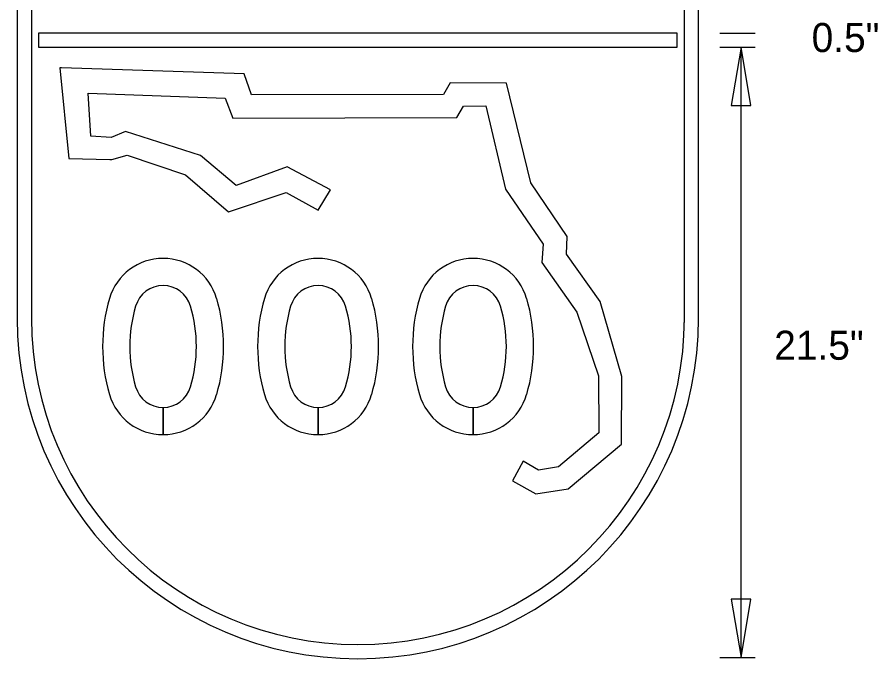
# Model space of a CAD drawing. Extents: x 0 to 770, y 0 to 495.
# Drawn here: x 659.4 to 763, y 209.5 to 286.8 of the extents above; entities that cross this region are included whole.
import ezdxf

# ---------------------------------------------------------------- set-up
doc = ezdxf.new("R2010")
doc.units = 0
for name, color, linetype in [('Default', 7, 'Continuous'), ('Dimension', 7, 'Continuous'), ('GSBWFill', 7, 'Continuous'), ('GSColorFill', 7, 'Continuous'), ('GSDims', 7, 'Continuous'), ('GSOutline', 7, 'Continuous'), ('IndexDetail_0', 7, 'Continuous'), ('TextStructures', 7, 'Continuous')]:
    doc.layers.add(name, color=color, linetype=linetype)

msp = doc.modelspace()

# ---------------------------------------------------------------- linework, layer by layer
at = {"layer": 'Default'}
for points in [[(664.53, 280.66), (665.6, 269.75), (670.52, 269.6)], [(664.71, 280.65), (664.53, 280.65)], [(719.01, 230.91), (721.8, 229.36), (725.71, 229.94), (732.12, 235.35), (732.16, 243.49), (729.56, 252.52), (725.53, 258.22), (725.61, 260.34), (721.2, 266.81), (718.29, 278.82), (711.52, 278.86), (710.72, 277.43), (687.6, 277.4), (686.7, 279.95), (664.71, 280.65)], [(670.76, 269.6), (672.6, 270.13), (679.65, 267.78), (684.8, 263.33), (691.76, 265.66), (695.61, 263.52), (697.08, 265.97), (691.88, 268.73), (685.73, 266.49), (681.45, 270.11), (672.42, 272.98), (670.7, 272.28), (668.24, 272.44), (667.92, 277.59), (684.43, 277), (685.34, 274.61), (712.29, 274.69)], [(712.29, 274.69), (713.1, 276.06), (715.81, 276.1), (718.18, 266.03), (722.7, 259.41), (722.54, 257.2), (726.76, 251.23), (729.36, 243.57)], [(670.52, 269.6), (670.76, 269.6)], [(729.36, 243.57), (729.4, 236.69)], [(729.4, 236.69), (724.56, 232.61), (722.13, 232.21), (720.29, 233.27), (719.01, 230.91)]]:
    msp.add_lwpolyline(points, dxfattribs=at)
at = {"layer": 'Dimension'}
for points in [[(746.53, 283.14), (745.35, 276.12), (747.72, 276.12)], [(746.53, 209.66), (747.72, 216.67), (745.35, 216.67)]]:
    msp.add_lwpolyline(points, close=True, dxfattribs=at)
at = {"layer": 'GSBWFill'}
for p, q in [((659.38, 300.06), (659.38, 250.5)), ((661.09, 300.06), (661.09, 250.5)), ((739.7, 249.97), (739.7, 300.06)), ((741.41, 250.27), (741.41, 300.06)), ((738.84, 284.85), (661.94, 284.85)), ((661.94, 284.85), (661.94, 283.14)), ((738.84, 283.14), (738.84, 284.85)), ((661.94, 283.14), (738.84, 283.14)), ((676.94, 239.77), (676.94, 236.49)), ((676.94, 236.49), (676.94, 239.77)), ((695.6, 239.77), (695.6, 236.49)), ((695.6, 236.49), (695.6, 239.77)), ((714.26, 236.49), (714.26, 239.77)), ((714.27, 239.77), (714.27, 236.49))]:
    msp.add_line(p, q, dxfattribs=at)
for centre, radius, start, end in [((676.94, 250.99), 6.72, 16.4025, 163.5975), ((695.6, 250.99), 6.72, 16.4025, 163.5975), ((714.26, 250.99), 6.72, 16.4025, 163.5975), ((676.94, 250.99), 3.44, 16.4025, 163.5975), ((695.6, 250.99), 3.44, 16.4025, 163.5975), ((714.26, 250.99), 3.44, 16.4025, 163.5975), ((690.17, 247.1), 20.51, 163.5975, 196.4025), ((663.72, 247.1), 20.51, 343.5975, 16.4025), ((708.83, 247.1), 20.51, 163.5975, 196.4025), ((682.38, 247.1), 20.51, 343.5975, 16.4025), ((727.49, 247.1), 20.51, 163.5975, 196.4025), ((701.04, 247.1), 20.51, 343.5975, 16.4025), ((690.17, 247.1), 17.23, 163.5975, 196.4025), ((663.72, 247.1), 17.23, 343.5975, 16.4025), ((708.83, 247.1), 17.23, 163.5975, 196.4025), ((682.38, 247.1), 17.23, 343.5975, 16.4025), ((727.49, 247.1), 17.23, 163.5975, 196.4025), ((701.04, 247.1), 17.23, 343.5975, 16.4025), ((676.94, 243.2), 3.44, 196.4025, 270), ((676.94, 243.2), 3.44, 270.0171, 343.5975), ((695.6, 243.2), 3.44, 196.4025, 270), ((695.6, 243.2), 3.44, 270.0171, 343.5975), ((714.26, 243.2), 3.44, 196.4025, 270), ((714.26, 243.2), 3.44, 270.0171, 343.5975), ((676.94, 243.2), 6.72, 196.4025, 270), ((676.94, 243.2), 6.72, 270.0087, 343.5975), ((695.6, 243.2), 6.72, 196.4025, 270), ((695.6, 243.2), 6.72, 270.0087, 343.5975), ((714.26, 243.2), 6.72, 196.4025, 270), ((714.26, 243.2), 6.72, 270.0087, 343.5975)]:
    msp.add_arc(centre, radius, start, end, dxfattribs=at)
at = {"layer": 'GSColorFill'}
for p, q in [((738.84, 284.85), (661.94, 284.85)), ((661.94, 284.85), (661.94, 283.14)), ((738.84, 283.14), (738.84, 284.85)), ((661.94, 283.14), (738.84, 283.14)), ((676.94, 239.77), (676.94, 236.49)), ((676.94, 236.49), (676.94, 239.77)), ((695.6, 239.77), (695.6, 236.49)), ((695.6, 236.49), (695.6, 239.77)), ((714.26, 236.49), (714.26, 239.77)), ((714.27, 239.77), (714.27, 236.49))]:
    msp.add_line(p, q, dxfattribs=at)
for centre, radius, start, end in [((676.94, 250.99), 6.72, 16.4025, 163.5975), ((695.6, 250.99), 6.72, 16.4025, 163.5975), ((714.26, 250.99), 6.72, 16.4025, 163.5975), ((676.94, 250.99), 3.44, 16.4025, 163.5975), ((695.6, 250.99), 3.44, 16.4025, 163.5975), ((714.26, 250.99), 3.44, 16.4025, 163.5975), ((690.17, 247.1), 20.51, 163.5975, 196.4025), ((663.72, 247.1), 20.51, 343.5975, 16.4025), ((708.83, 247.1), 20.51, 163.5975, 196.4025), ((682.38, 247.1), 20.51, 343.5975, 16.4025), ((727.49, 247.1), 20.51, 163.5975, 196.4025), ((701.04, 247.1), 20.51, 343.5975, 16.4025), ((690.17, 247.1), 17.23, 163.5975, 196.4025), ((663.72, 247.1), 17.23, 343.5975, 16.4025), ((708.83, 247.1), 17.23, 163.5975, 196.4025), ((682.38, 247.1), 17.23, 343.5975, 16.4025), ((727.49, 247.1), 17.23, 163.5975, 196.4025), ((701.04, 247.1), 17.23, 343.5975, 16.4025), ((676.94, 243.2), 3.44, 196.4025, 270), ((676.94, 243.2), 3.44, 270.0171, 343.5975), ((695.6, 243.2), 3.44, 196.4025, 270), ((695.6, 243.2), 3.44, 270.0171, 343.5975), ((714.26, 243.2), 3.44, 196.4025, 270), ((714.26, 243.2), 3.44, 270.0171, 343.5975), ((676.94, 243.2), 6.72, 196.4025, 270), ((676.94, 243.2), 6.72, 270.0087, 343.5975), ((695.6, 243.2), 6.72, 196.4025, 270), ((695.6, 243.2), 6.72, 270.0087, 343.5975), ((714.26, 243.2), 6.72, 196.4025, 270), ((714.26, 243.2), 6.72, 270.0087, 343.5975)]:
    msp.add_arc(centre, radius, start, end, dxfattribs=at)
at = {"layer": 'GSDims'}
for p, q in [((743.97, 284.85), (748.24, 284.85)), ((743.97, 284.85), (748.24, 284.85)), ((743.97, 283.14), (748.24, 283.14)), ((743.97, 283.14), (748.24, 283.14)), ((746.53, 209.66), (746.53, 283.14)), ((743.97, 209.66), (748.24, 209.66))]:
    msp.add_line(p, q, dxfattribs=at)
at = {"layer": 'GSOutline'}
for p, q in [((738.84, 284.85), (661.94, 284.85)), ((661.94, 284.85), (661.94, 283.14)), ((738.84, 283.14), (738.84, 284.85)), ((661.94, 283.14), (738.84, 283.14))]:
    msp.add_line(p, q, dxfattribs=at)
for centre, radius, start, end in [((676.94, 250.99), 6.72, 16.4025, 163.5975), ((695.6, 250.99), 6.72, 16.4025, 163.5975), ((714.26, 250.99), 6.72, 16.4025, 163.5975), ((676.94, 250.99), 3.44, 16.4025, 163.5975), ((695.6, 250.99), 3.44, 16.4025, 163.5975), ((714.26, 250.99), 3.44, 16.4025, 163.5975), ((690.17, 247.1), 20.51, 163.5975, 196.4025), ((663.72, 247.1), 20.51, 343.5975, 16.4025), ((708.83, 247.1), 20.51, 163.5975, 196.4025), ((682.38, 247.1), 20.51, 343.5975, 16.4025), ((727.49, 247.1), 20.51, 163.5975, 196.4025), ((701.04, 247.1), 20.51, 343.5975, 16.4025), ((690.17, 247.1), 17.23, 163.5975, 196.4025), ((663.72, 247.1), 17.23, 343.5975, 16.4025), ((708.83, 247.1), 17.23, 163.5975, 196.4025), ((682.38, 247.1), 17.23, 343.5975, 16.4025), ((727.49, 247.1), 17.23, 163.5975, 196.4025), ((701.04, 247.1), 17.23, 343.5975, 16.4025), ((676.94, 243.2), 3.44, 196.4025, 343.5975), ((695.6, 243.2), 3.44, 196.4025, 343.5975), ((714.26, 243.2), 3.44, 196.4025, 343.5975), ((676.94, 243.2), 6.72, 196.4025, 343.5975), ((695.6, 243.2), 6.72, 196.4025, 343.5975), ((714.26, 243.2), 6.72, 196.4025, 343.5975)]:
    msp.add_arc(centre, radius, start, end, dxfattribs=at)
at = {"layer": 'IndexDetail_0'}
for centre, radius in [((700.39, 250.5), 41.01), ((700.4, 250.5), 39.3)]:
    msp.add_arc(centre, radius, 180, 0, dxfattribs=at)

# ---------------------------------------------------------------- texts
at = {"layer": 'TextStructures'}
for s, p in [('0.5"', (755.02, 282.56)), ('21.5"', (750.52, 245.5))]:
    msp.add_text(s, height=3.5, dxfattribs=at).set_placement(p)

doc.saveas('drawing.dxf')
